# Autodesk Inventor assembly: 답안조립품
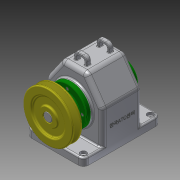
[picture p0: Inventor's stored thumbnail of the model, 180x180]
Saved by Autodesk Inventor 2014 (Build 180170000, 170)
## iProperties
Created: 2016-12
Part Number: 답안조립품
Document SubType Name: Assembly
Designer: USER
Author: USER
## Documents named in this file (15)
- C:\Users\USER\Desktop\461208V1018\답안조립품.iam
- C:\Users\USER\Desktop\461208V1018\V-벨트풀리.ipt
- C:\Users\USER\Desktop\461208V1018\뒤커버.ipt
- C:\Users\USER\Desktop\461208V1018\멈춤나사 - M4x10.ipt
- C:\Users\USER\Desktop\461208V1018\베어링 6203.ipt
- C:\Users\USER\Desktop\461208V1018\본체.ipt
- C:\Users\USER\Desktop\461208V1018\볼트 M3 x 8.ipt
- C:\Users\USER\Desktop\461208V1018\볼트 M3 x 10.ipt
- C:\Users\USER\Desktop\461208V1018\부시.ipt
- C:\Users\USER\Desktop\461208V1018\스퍼기어.ipt
- C:\Users\USER\Desktop\461208V1018\앞커버.ipt
- C:\Users\USER\Desktop\461208V1018\오일씰 28 40 8.ipt
- C:\Users\USER\Desktop\461208V1018\축.ipt
- C:\Users\USER\Desktop\461208V1018\키 - 5 x 5 x 18.ipt
- C:\Users\USER\Desktop\461208V1018\키 - 6 x 6 x 22.ipt
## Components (9 placed, 3 different names)
1. V-벨트풀리:1
2. ISO 4762 M3 x 10:1
3. ISO 4762 M3 x 10:2
4. ISO 4762 M3 x 10:3
5. ISO 4762 M3 x 10:4
6. ISO 4762 M3 x 8:1
7. ISO 4762 M3 x 8:2
8. ISO 4762 M3 x 8:3
9. ISO 4762 M3 x 8:4
